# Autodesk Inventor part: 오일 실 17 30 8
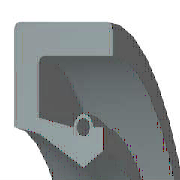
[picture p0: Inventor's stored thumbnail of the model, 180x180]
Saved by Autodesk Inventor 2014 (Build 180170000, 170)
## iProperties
IsCustomPart: 1
Created: 2012-02
Part Number: 오일 실 17 30 8
Material: 고무
Description: 오일-실
Document SubType Name: Modeling
Standard: KS B 2804
Designer: mduedu
Standards Organization: KS
Language: ko-KR
Size Designation: S - 17 30 8
Categories: <MemberInstance><Categories><Category DisplayName="샤프트 부품" InternalName="7f7aeb1f-a693-4053-b835-cee3144e0d98" Mnemonic="SHFT"><Category DisplayName="실링" Intern
Density: 0.93 g/cm^3
Appearance: 고무 - 검은색 - 버전 1.1
Author: mduedu
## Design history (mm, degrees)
revolve "본체" stored, may be unused: angle "d17" = 90 deg
revolve "스프링1" stored, may be unused: angle "d18" = 90 deg
body "Solid1"
sketch "스케치1"
  geometry: L1 (0, 15)-(8, 15); L2 (8, 15)-(8, 13.75); L3 (8, 13.75)-(1.75, 13.75); L4 (0, 15)-(0, 10.6); L5 (0, 10.6)-(1.75, 10.25); L6 (1.75, 10.25)-(4.9, 8.5); L7 (4.9, 8.5)-(0, 8.5); L8 (6.3, 9.375)-(6.3, 10.6); L9 (0, 0)-(9.586, 0) reference; L10 (4.9, 8.5)-(6.3, 9.375); L11 (0, 18)-(0, -3) reference; L12 (-1.917, 0)-(11.503, 0) reference; L13 (4.2, 10.6)-(1.75, 11.09); L14 (1.75, 11.09)-(1.75, 13.75); L15 (6.3, 10.6)-(5.6, 10.6); C1 r 0.455 at (4.9, 10.6); A1 r 0.7 centre (4.9, 10.6) between (5.6, 10.6) and (4.2, 10.6)
  constraints: 26 end point, 5 horizontal alignment, 4 perpendicular, 2 centre point, 2 collinear, 2 horizontal, 2 parallel, 2 point on circle, 2 point on line, 2 vertical alignment, 1 coincident
  dimensions: "d0" = 30 diameter of L1 L9 (= SD2); "d1" = 18.75 diameter of L8.start L9 (= ABDM); "d2" = 1.25 distance of L1.end L2.end (computed from SD); "d3" = 0.91 diameter of C1 (= SPDI); "d4" = 1.4 diameter of A1 (= SPDA); "d5" = 17 diameter of L6.end L9 (= NND); "d6" = 20.5 diameter of L5.end L9 (= TKDM); "d7" = 21.2 diameter of L4.end L9 (= HLDM); "d8" = 4.9 distance from line of C1.centre L4 (= SPDST); "d9" = 6.3 distance between parallel lines of L8 L4 (= SDI); "d10" = 8 distance between parallel lines of L2 L4 (= SWDT); "d12" = 1.75 distance between parallel lines of L14 L4 (= SD)
fillet "모깎기1" dims "d11" = 0.5 (= RR)
other parameters: "SD2" = 30 [user parameter; used in 1 equation term], "SWDT" = 8 [user parameter; used in 1 equation term], "RR" = 0.5 [user parameter; used in 1 equation term], "SD" = 1.75 [user parameter; used in 2 equation terms], "NND" = 17 [user parameter; used in 1 equation term], "SPDA" = 1.4 [user parameter; used in 1 equation term], "SPDI" = 0.91 [user parameter; used in 1 equation term], "TKDM" = 20.5 [user parameter; used in 1 equation term], "HLDM" = 21.2 [user parameter; used in 1 equation term], "ABDM" = 18.75 [user parameter; used in 1 equation term], "SDI" = 6.3 [user parameter; used in 1 equation term], "SPDST" = 4.9 [user parameter; used in 1 equation term], "d13" = 0, "d14" = 0, "d15" = 0, "LAB" = 0.35 [user parameter]
